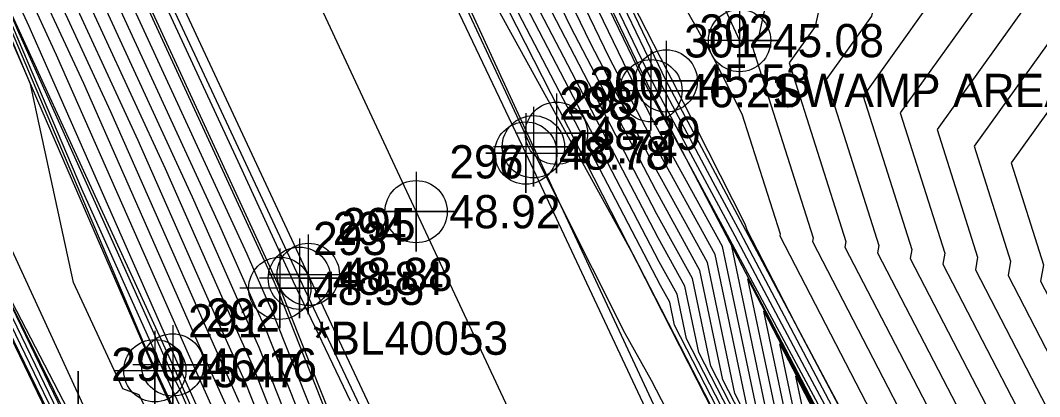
# Model space of a CAD drawing. Extents: x 2090860 to 2091277, y 159470 to 160080.
# Drawn here: x 2090993 to 2091069.7, y 159834.6 to 159862.9 of the extents above; entities that cross this region are included whole.
import ezdxf

# ---------------------------------------------------------------- set-up
doc = ezdxf.new("R2010")
doc.units = 0
for name, color, linetype in [('DTM Contours Major', 7, 'Continuous'), ('DTM Contours Minor', 7, 'Continuous'), ('Exist DTM Breakline', 7, 'Continuous'), ('Exist DTM Breakline Cogo Comment', 7, 'Continuous'), ('Exist DTM Breakline Cogo Elevation', 7, 'Continuous'), ('Exist DTM Breakline Cogo Number', 7, 'Continuous'), ('Exist DTM Breakline Cogo Point CELL', 7, 'Continuous'), ('Exist DTM Breakline Underwater', 7, 'Continuous'), ('Exist DTM Crownline', 7, 'Continuous'), ('Exist DTM Crownline Cogo Elevation', 7, 'Continuous'), ('Exist DTM Crownline Cogo Number', 7, 'Continuous'), ('Exist DTM Crownline Cogo Point CELL', 7, 'Continuous'), ('Exist Hydro Swamp or Marsh', 7, 'Continuous'), ('Exist Hydro Swamp or Marsh Cogo Number', 7, 'Continuous'), ('Exist Roads EOP', 7, 'Continuous'), ('Exist Roads EOP Cogo Elevation', 7, 'Continuous'), ('Exist Roads EOP Cogo Number', 7, 'Continuous'), ('Exist Roads EOP Cogo Point CELL', 7, 'Continuous'), ('Exist Roads EOT', 7, 'Continuous'), ('Exist Roads EOT Cogo Elevation', 7, 'Continuous'), ('Exist Roads EOT Cogo Number', 7, 'Continuous'), ('Exist Roads EOT Cogo Point CELL', 7, 'Continuous')]:
    doc.layers.add(name, color=color, linetype=linetype)

msp = doc.modelspace()

# ---------------------------------------------------------------- linework, layer by layer
at = {"layer": 'DTM Contours Major'}
for points in [[(2091039.965, 159928.181), (2091029.722, 159901.932), (2091029.836, 159894.927), (2091030.644, 159893.334), (2091041.091, 159874.328), (2091046.743, 159874.324), (2091051.278, 159874.322), (2091048.513, 159861.61), (2091048.021, 159860.923), (2091052.613, 159846.512), (2091052.563, 159846.236), (2091064.701, 159822.801), (2091063.816, 159819.49), (2091056.743, 159812.832), (2091055.874, 159811.447), (2091055.801, 159811.406), (2091054.881, 159810.97), (2091050.569, 159808.882), (2091033.907, 159797.012), (2091031.476, 159794.619), (2091026.533, 159778.36)], [(2091091.582, 159898.637), (2091075.464, 159895.754), (2091071.361, 159891.649), (2091065.515, 159864.769), (2091059.162, 159855.905), (2091062.527, 159845.344), (2091062.382, 159844.528), (2091071.24, 159827.424), (2091068.468, 159817.052), (2091062.553, 159811.484), (2091060.259, 159801.479), (2091046.876, 159791.945), (2091037.586, 159782.801), (2091031.987, 159764.384), (2091026.688, 159760.214), (2091021.294, 159752.688), (2091014.874, 159747.469), (2091001.671, 159730.125), (2090998.416, 159727.263), (2090990.823, 159719.668), (2090976.25, 159706.989)], [(2091056.078, 159816.651), (2091046.739, 159834.797), (2091044.672, 159844.658), (2091040.694, 159851.881), (2091035.836, 159861.213), (2091027.499, 159878.464)], [(2090991.853, 159864.196), (2090992.701, 159862.198), (2091004.114, 159836.848), (2091004.895, 159835.174), (2091007.518, 159829.269), (2091018.331, 159804.925), (2091019.741, 159801.878), (2091021.206, 159801.236), (2091025.093, 159800.189), (2091028.857, 159799.035), (2091029.349, 159799.339), (2091029.689, 159799.398), (2091044.087, 159806.371), (2091055.495, 159811.774), (2091056.395, 159812.282), (2091061.025, 159819.665), (2091060.533, 159819.671), (2091060.876, 159820.18), (2091051.784, 159837.119), (2091046.749, 159846.634), (2091042.53, 159854.466), (2091040.766, 159857.8), (2091031.335, 159877.368)], [(2091016.707, 159800.202), (2091008.385, 159811.907), (2091004.989, 159818.475), (2091002.257, 159829.041), (2091000.514, 159832.567), (2090997.856, 159833.556), (2090989.841, 159850.886), (2090987.897, 159859.839), (2090982.037, 159867.754), (2090974.898, 159876.535), (2090983.754, 159858.196), (2090986.806, 159851.928), (2090996.121, 159832.681), (2090997.829, 159829.173), (2090999.89, 159824.931), (2091004.415, 159815.535), (2091007.296, 159809.554), (2091015.202, 159792.842), (2091016.707, 159800.202)], [(2090998.152, 159868.688), (2091007.947, 159847.443), (2091010.62, 159841.379), (2091011.396, 159839.656), (2091019.854, 159818.29)], [(2090994.954, 159866.398), (2090999.747, 159856.003), (2091007.255, 159838.974), (2091009.433, 159834.136)], [(2091055.311, 159815.182), (2091043.096, 159838.914), (2091042.395, 159842.26), (2091041.045, 159844.711), (2091030.068, 159865.795)], [(2091047.708, 159843.434), (2091059.851, 159820.055), (2091059.262, 159819.226), (2091056.846, 159818.12), (2091050.382, 159830.679), (2091047.708, 159843.434)]]:
    msp.add_lwpolyline(points, dxfattribs=at)
at = {"layer": 'DTM Contours Minor'}
for points in [[(2090953.056, 159921.956), (2090965.045, 159895.337), (2090965.357, 159894.662), (2090965.917, 159893.402), (2090966.117, 159891.569), (2090966.399, 159891.209), (2090966.744, 159891.353), (2090970.598, 159883.648), (2090979.253, 159865.886), (2090979.998, 159864.343), (2090992.069, 159839.553), (2090993.271, 159837.069), (2090997.157, 159829.086), (2091001.847, 159819.434), (2091003.887, 159815.198), (2091014.815, 159792.51), (2091016.869, 159788.257), (2091017.431, 159786.838), (2091024.63, 159765.903)], [(2091018.49, 159801.202), (2091016.342, 159804.224), (2091005.914, 159824.395), (2091004.745, 159828.914), (2091001.892, 159834.689), (2091000.663, 159835.146), (2090996.957, 159843.159), (2090993.719, 159858.066), (2090991.183, 159864.043), (2090990.784, 159864.918), (2090986.104, 159875.843), (2090983.691, 159880.804), (2090975.225, 159897.621), (2090972.537, 159899.282), (2090971.355, 159899.978), (2090971.029, 159900.712), (2090971.838, 159903.298), (2090965.559, 159913.825)], [(2090957.425, 159912.812), (2090965.766, 159894.719), (2090966.215, 159893.707), (2090967.091, 159891.809), (2090969.426, 159886.946), (2090975.022, 159875.464), (2090981.876, 159861.269), (2090989.438, 159845.741), (2090994.696, 159834.875), (2090997.493, 159829.13), (2091000.868, 159822.182), (2091004.151, 159815.366), (2091012.999, 159796.996), (2091016.233, 159790.161), (2091018.49, 159801.202)], [(2091026.968, 159913.295), (2091027.29, 159893.598), (2091029.561, 159889.119), (2091036.393, 159876.69), (2091042.848, 159864.079), (2091045.034, 159860.22), (2091047.258, 159855.832), (2091050.134, 159846.804), (2091050.109, 159846.662), (2091063.066, 159821.645), (2091062.653, 159820.099), (2091059.35, 159816.99), (2091056.004, 159811.656), (2091055.725, 159811.498), (2091052.183, 159809.82), (2091035.577, 159801.778), (2091030.665, 159798.279), (2091029.949, 159797.574), (2091028.492, 159792.781), (2091019.078, 159782.234), (2091024.701, 159765.882)], [(2091085.63, 159904.476), (2091061.277, 159900.12), (2091060.882, 159899.725), (2091052.763, 159862.4), (2091050.806, 159859.669), (2091055.091, 159846.22), (2091055.018, 159845.809), (2091066.336, 159823.957), (2091064.979, 159818.88), (2091057.025, 159811.393), (2091056.616, 159809.613), (2091037.15, 159795.745), (2091033.004, 159791.665), (2091025.134, 159765.782), (2091024.911, 159765.606), (2091017.656, 159755.482), (2091016.238, 159754.329), (2090999.201, 159731.949), (2090995.001, 159728.257), (2090991.695, 159724.95), (2090972.197, 159707.986)], [(2091087.614, 159902.53), (2091066.006, 159898.665), (2091064.375, 159897.033), (2091057.014, 159863.189), (2091053.591, 159858.414), (2091057.57, 159845.928), (2091057.473, 159845.382), (2091067.971, 159825.113), (2091066.142, 159818.271), (2091058.867, 159811.424), (2091057.831, 159806.902), (2091040.392, 159794.478), (2091034.531, 159788.71), (2091027.419, 159765.316), (2091025.503, 159763.809), (2091018.868, 159754.551), (2091015.783, 159752.042), (2091000.024, 159731.341), (2090996.139, 159727.925), (2090991.404, 159723.189), (2090973.548, 159707.654)], [(2091089.598, 159900.583), (2091070.735, 159897.209), (2091067.868, 159894.341), (2091061.264, 159863.979), (2091056.377, 159857.16), (2091060.048, 159845.636), (2091059.927, 159844.955), (2091069.606, 159826.269), (2091067.305, 159817.661), (2091060.71, 159811.454), (2091059.045, 159804.19), (2091043.634, 159793.212), (2091036.059, 159785.755), (2091029.703, 159764.85), (2091026.095, 159762.012), (2091020.081, 159753.62), (2091015.328, 159749.755), (2091000.847, 159730.733), (2090997.277, 159727.594), (2090991.114, 159721.429), (2090974.899, 159707.322)], [(2091093.566, 159896.69), (2091080.192, 159894.298), (2091074.854, 159888.957), (2091069.765, 159865.558), (2091061.947, 159854.65), (2091065.005, 159845.052), (2091064.837, 159844.101), (2091072.875, 159828.58), (2091069.631, 159816.443), (2091064.396, 159811.515), (2091061.473, 159798.767), (2091050.118, 159790.678), (2091039.113, 159779.846), (2091034.271, 159763.918), (2091027.28, 159758.417), (2091022.507, 159751.757), (2091014.419, 159745.182), (2091002.494, 159729.516), (2090999.554, 159726.932), (2090990.532, 159717.907), (2090977.601, 159706.657)], [(2091095.549, 159894.744), (2091084.921, 159892.843), (2091078.348, 159886.266), (2091074.015, 159866.348), (2091064.733, 159853.396), (2091067.484, 159844.76), (2091067.291, 159843.674), (2091074.51, 159829.736), (2091070.794, 159815.833), (2091066.238, 159811.545), (2091062.688, 159796.056), (2091053.36, 159789.411), (2091040.641, 159776.892), (2091036.555, 159763.452), (2091027.872, 159756.62), (2091023.719, 159750.826), (2091013.964, 159742.895), (2091003.317, 159728.908), (2091000.692, 159726.601), (2090990.241, 159716.147), (2090978.952, 159706.325)], [(2091097.533, 159892.797), (2091089.65, 159891.387), (2091081.841, 159883.574), (2091078.266, 159867.137), (2091067.518, 159852.141), (2091069.963, 159844.468), (2091069.746, 159843.247), (2091076.145, 159830.892), (2091071.957, 159815.224), (2091068.081, 159811.575), (2091063.902, 159793.344), (2091056.602, 159788.144), (2091042.168, 159773.937), (2091038.839, 159762.987), (2091028.464, 159754.823), (2091024.932, 159749.895), (2091013.509, 159740.608), (2091004.14, 159728.3), (2091001.83, 159726.269), (2090989.951, 159714.386), (2090980.303, 159705.993)], [(2090992.556, 159864.681), (2090993.597, 159862.423), (2091004.731, 159837.17), (2091007.961, 159829.995), (2091008.468, 159828.714), (2091020.08, 159802.837), (2091021.254, 159801.443), (2091021.996, 159801.118), (2091023.46, 159800.723), (2091028.681, 159799.123), (2091029.364, 159799.544), (2091029.836, 159799.626), (2091041.388, 159805.221), (2091055.419, 159811.866), (2091056.526, 159812.491), (2091060.739, 159819.209), (2091060.015, 159819.218), (2091060.519, 159819.967), (2091047.146, 159844.881), (2091046.348, 159846.389), (2091043.245, 159852.15), (2091040.431, 159857.259), (2091040.162, 159857.776), (2091027.446, 159884.088)], [(2091048.56, 159832.738), (2091045.81, 159845.857), (2091040.519, 159855.466), (2091038.72, 159858.921), (2091027.464, 159882.213)], [(2091052.347, 159812.818), (2091040.46, 159835.77), (2091038.477, 159839.311), (2091033.536, 159849.139), (2091031.44, 159853.253), (2091029.679, 159857.091), (2091018.757, 159880.423)], [(2091047.65, 159833.767), (2091045.241, 159845.257), (2091040.607, 159853.673), (2091037.278, 159860.067), (2091027.481, 159880.338)], [(2091055.886, 159816.284), (2091045.828, 159835.826), (2091044.102, 159844.058), (2091040.782, 159850.088), (2091034.394, 159862.358), (2091027.517, 159876.589)], [(2091061.059, 159821.595), (2091051.606, 159839.459), (2091047.654, 159847.089), (2091047.655, 159847.096), (2091047.517, 159847.529), (2091041.945, 159858.526), (2091041.704, 159858.952), (2091034.703, 159872.628)], [(2091000.895, 159870.46), (2091009.465, 159851.941), (2091013.483, 159843.225), (2091017.769, 159834.238)], [(2090999.751, 159869.832), (2091012.046, 159843.163), (2091012.303, 159842.582), (2091012.377, 159842.416), (2091023.107, 159815.311)], [(2090998.952, 159869.26), (2091009.997, 159845.303), (2091011.461, 159841.98), (2091011.886, 159841.036), (2091021.481, 159816.8)], [(2090996.553, 159867.543), (2091003.847, 159851.723), (2091008.937, 159840.176), (2091010.414, 159836.896), (2091016.601, 159821.268)], [(2090997.353, 159868.115), (2091005.897, 159849.583), (2091009.779, 159840.778), (2091010.905, 159838.276), (2091018.227, 159819.779)], [(2090991.629, 159864.145), (2090997.549, 159850.196), (2091003.629, 159836.691), (2091005.654, 159832.353), (2091007.113, 159829.069), (2091013.126, 159815.531), (2091019.504, 159801.754), (2091020.416, 159801.354), (2091026.726, 159799.654), (2091029.032, 159798.948), (2091029.334, 159799.133), (2091029.542, 159799.17), (2091046.785, 159807.521), (2091055.572, 159811.682), (2091056.265, 159812.074), (2091061.312, 159820.121), (2091061.051, 159820.124), (2091061.233, 159820.393), (2091056.421, 159829.357), (2091047.15, 159846.879), (2091045.095, 159850.693), (2091041.19, 159858.075), (2091036.787, 159867.212)], [(2090995.754, 159866.971), (2091001.797, 159853.863), (2091008.096, 159839.575), (2091009.924, 159835.516), (2091014.974, 159822.757)], [(2091055.119, 159814.815), (2091042.185, 159839.944), (2091041.825, 159841.661), (2091041.133, 159842.918), (2091028.626, 159866.941)], [(2090993.355, 159865.254), (2090995.647, 159860.283), (2091005.572, 159837.771), (2091008.452, 159831.375)], [(2090994.155, 159865.826), (2090997.697, 159858.143), (2091006.414, 159838.372), (2091008.943, 159832.756)], [(2091054.927, 159814.447), (2091041.274, 159840.973), (2091041.256, 159841.061), (2091041.221, 159841.126), (2091039.076, 159845.244), (2091028.516, 159864.43)], [(2091055.503, 159815.549), (2091044.007, 159837.885), (2091042.964, 159842.86), (2091040.958, 159846.503), (2091031.51, 159864.649)], [(2090991.406, 159864.094), (2091002.397, 159838.193), (2091003.144, 159836.535), (2091006.413, 159829.532)], [(2091055.694, 159815.916), (2091044.917, 159836.856), (2091043.533, 159843.459), (2091040.87, 159848.296), (2091032.952, 159863.504)], [(2090989.86, 159846.37), (2090997.915, 159830.901), (2090999.137, 159830.446), (2090999.768, 159829.169), (2091001.594, 159822.11), (2090998.911, 159827.68), (2090998.164, 159829.216), (2090997.546, 159830.487), (2090989.86, 159846.37)], [(2091046.5, 159845.882), (2091059.993, 159819.903), (2091059.339, 159818.981), (2091056.654, 159817.753), (2091049.471, 159831.708), (2091046.5, 159845.882)], [(2091048.916, 159840.986), (2091059.709, 159820.207), (2091059.185, 159819.47), (2091057.038, 159818.487), (2091051.292, 159829.649), (2091048.916, 159840.986)], [(2091050.124, 159838.538), (2091059.566, 159820.359), (2091059.108, 159819.714), (2091057.229, 159818.854), (2091052.203, 159828.62), (2091050.124, 159838.538)], [(2091051.332, 159836.09), (2091059.424, 159820.511), (2091059.031, 159819.958), (2091057.421, 159819.222), (2091053.114, 159827.59), (2091051.332, 159836.09)]]:
    msp.add_lwpolyline(points, dxfattribs=at)
at = {"layer": 'Exist DTM Breakline'}
for p, q in [((2090966.689, 159891.716), (2090997.039, 159829.071)), ((2090998.355, 159829.241), (2090967.299, 159891.857)), ((2091012.481, 159842.709), (2091028.915, 159801.572))]:
    msp.add_line(p, q, dxfattribs=at)
for points in [[(2091060.143, 159819.743), (2091040.416, 159857.574), (2091023.862, 159892.084), (2091004.981, 159933.927), (2090988.922, 159970.746), (2090947.972, 160061.797)], [(2091061.634, 159820.633), (2091041.562, 159858.316), (2091025.181, 159892.498), (2091005.429, 159934.281), (2090989.687, 159971.201), (2090948.616, 160062.008)], [(2091054.851, 159814.302), (2091016.781, 159888.977), (2090997.773, 159930.425), (2090980.346, 159966.514), (2090937.845, 160056.578)], [(2091012.481, 159842.709), (2090995.611, 159879.293), (2090976.725, 159918.896), (2090959.8, 159955.653), (2090940.36, 159997.15), (2090917.627, 160046.575)], [(2091019.111, 159801.55), (2091003.076, 159836.513), (2090986.016, 159875.809), (2090966.872, 159914.505), (2090949.073, 159951.294), (2090930.109, 159992.15), (2090906.432, 160041.549)], [(2091019.809, 159801.913), (2091004.418, 159836.946), (2090986.475, 159875.987), (2090967.517, 159915.028), (2090950.041, 159951.449), (2090930.695, 159992.433), (2090908.049, 160042.233)]]:
    msp.add_lwpolyline(points, dxfattribs=at)
at = {"layer": 'Exist DTM Breakline Cogo Point CELL'}
for points in [[(2091047.085, 159864.345), (2091047.085, 159858.345), (2091047.085, 159861.345), (2091050.085, 159861.345), (2091044.085, 159861.345)], [(2091041.562, 159861.316), (2091041.562, 159855.316), (2091041.562, 159858.316), (2091044.562, 159858.316), (2091038.562, 159858.316)], [(2091040.416, 159860.574), (2091040.416, 159854.574), (2091040.416, 159857.574), (2091043.416, 159857.574), (2091037.416, 159857.574)], [(2091033.298, 159857.372), (2091033.298, 159851.372), (2091033.298, 159854.372), (2091036.298, 159854.372), (2091030.298, 159854.372)], [(2091012.481, 159845.709), (2091012.481, 159839.709), (2091012.481, 159842.709), (2091015.481, 159842.709), (2091009.481, 159842.709)], [(2091004.418, 159839.946), (2091004.418, 159833.946), (2091004.418, 159836.946), (2091007.418, 159836.946), (2091001.418, 159836.946)], [(2091003.076, 159839.513), (2091003.076, 159833.513), (2091003.076, 159836.513), (2091006.076, 159836.513), (2091000.076, 159836.513)]]:
    msp.add_lwpolyline(points, dxfattribs=at)
for centre in [(2091047.085, 159861.345), (2091041.562, 159858.316), (2091040.416, 159857.574), (2091033.298, 159854.372), (2091012.481, 159842.709), (2091004.418, 159836.946), (2091003.076, 159836.513)]:
    msp.add_circle(centre, 2.344, dxfattribs=at)
at = {"layer": 'Exist DTM Breakline Underwater'}
msp.add_lwpolyline([(2091025.272, 159920.294), (2091031.242, 159895.66), (2091047.085, 159861.345)], dxfattribs=at)
at = {"layer": 'Exist DTM Crownline'}
msp.add_lwpolyline([(2091041.896, 159807.58), (2091022.738, 159848.476), (2091006.16, 159884.052), (2090987.202, 159924.29), (2090970.349, 159960.929), (2090951.234, 160001.943), (2090928.333, 160051.748)], dxfattribs=at)
at = {"layer": 'Exist DTM Crownline Cogo Point CELL'}
msp.add_lwpolyline([(2091022.738, 159851.476), (2091022.738, 159845.476), (2091022.738, 159848.476), (2091025.738, 159848.476), (2091019.738, 159848.476)], dxfattribs=at)
msp.add_circle((2091022.738, 159848.476), 2.344, dxfattribs=at)
at = {"layer": 'Exist Hydro Swamp or Marsh'}
msp.add_lwpolyline([(2090994.07, 159830.564), (2090997.296, 159830.564), (2090997.296, 159836.481), (2090997.296, 159830.564), (2091000.521, 159830.564)], dxfattribs=at)
at = {"layer": 'Exist Roads EOP'}
for points in [[(2091050.887, 159811.953), (2091031.567, 159853.358), (2091015.44, 159888.433), (2090996.018, 159929.558), (2090979.118, 159965.859), (2090960.144, 160006.791), (2090936.877, 160056.11)], [(2091032.873, 159803.467), (2091013.956, 159843.468), (2090996.901, 159879.939), (2090978.321, 159919.673), (2090961.239, 159956.493), (2090941.84, 159997.888), (2090918.792, 160047.284)]]:
    msp.add_lwpolyline(points, dxfattribs=at)
at = {"layer": 'Exist Roads EOP Cogo Point CELL'}
for points in [[(2091031.567, 159856.358), (2091031.567, 159850.358), (2091031.567, 159853.358), (2091034.567, 159853.358), (2091028.567, 159853.358)], [(2091013.956, 159846.468), (2091013.956, 159840.468), (2091013.956, 159843.468), (2091016.956, 159843.468), (2091010.956, 159843.468)]]:
    msp.add_lwpolyline(points, dxfattribs=at)
for centre in [(2091031.567, 159853.358), (2091013.956, 159843.468)]:
    msp.add_circle(centre, 2.344, dxfattribs=at)
at = {"layer": 'Exist Roads EOT'}
for points in [[(2091050.358, 159811.619), (2091030.997, 159852.885), (2091014.318, 159887.944), (2090995.228, 159929.102), (2090978.274, 159965.509), (2090959.414, 160006.451), (2090936.296, 160055.791)], [(2091033.429, 159803.706), (2091014.624, 159843.758), (2090997.608, 159880.208), (2090978.895, 159919.952), (2090961.789, 159956.632), (2090942.516, 159998.302), (2090919.608, 160047.643)]]:
    msp.add_lwpolyline(points, dxfattribs=at)
at = {"layer": 'Exist Roads EOT Cogo Point CELL'}
for points in [[(2091030.997, 159855.885), (2091030.997, 159849.885), (2091030.997, 159852.885), (2091027.997, 159852.885), (2091033.997, 159852.885)], [(2091022.738, 159851.476), (2091022.738, 159845.476), (2091022.738, 159848.476), (2091019.738, 159848.476), (2091025.738, 159848.476)], [(2091014.624, 159846.758), (2091014.624, 159840.758), (2091014.624, 159843.758), (2091011.624, 159843.758), (2091017.624, 159843.758)]]:
    msp.add_lwpolyline(points, dxfattribs=at)
for centre in [(2091030.997, 159852.885), (2091022.738, 159848.476), (2091014.624, 159843.758)]:
    msp.add_circle(centre, 2.344, dxfattribs=at)

# ---------------------------------------------------------------- texts
at = {"layer": 'Exist DTM Breakline Cogo Comment'}
for s, p in [('SWAMP AREA', (2091049.585, 159856.345)), ('*BL40053', (2091014.981, 159837.709))]:
    msp.add_text(s, height=2.5, dxfattribs=at).set_placement(p)
at = {"layer": 'Exist DTM Breakline Cogo Elevation'}
for s, p in [('45.08', (2091049.585, 159860.095)), ('45.53', (2091044.062, 159857.066)), ('46.21', (2091042.916, 159856.324)), ('48.39', (2091035.798, 159853.122)), ('48.55', (2091014.981, 159841.459)), ('45.47', (2091005.576, 159835.263)), ('46.16', (2091006.918, 159835.696))]:
    msp.add_text(s, height=2.5, dxfattribs=at).set_placement(p)
at = {"layer": 'Exist DTM Breakline Cogo Number'}
for s, p in [('302', (2091044.062, 159860.816)), ('301', (2091042.916, 159860.074)), ('300', (2091035.798, 159856.872)), ('293', (2091014.981, 159845.209)), ('291', (2091005.576, 159839.013)), ('292', (2091006.918, 159839.446))]:
    msp.add_text(s, height=2.5, dxfattribs=at).set_placement(p)
at = {"layer": 'Exist DTM Crownline Cogo Elevation'}
msp.add_text('48.92', height=2.5, dxfattribs=at).set_placement((2091025.238, 159847.226))
at = {"layer": 'Exist DTM Crownline Cogo Number'}
msp.add_text('297', height=2.5, dxfattribs=at).set_placement((2091025.238, 159850.976))
at = {"layer": 'Exist Hydro Swamp or Marsh Cogo Number'}
msp.add_text('290', height=2.5, dxfattribs=at).set_placement((2090999.795, 159835.738))
at = {"layer": 'Exist Roads EOP Cogo Elevation'}
for s, p in [('48.74', (2091034.067, 159852.108)), ('48.84', (2091016.456, 159842.218))]:
    msp.add_text(s, height=2.5, dxfattribs=at).set_placement(p)
at = {"layer": 'Exist Roads EOP Cogo Number'}
for s, p in [('299', (2091034.067, 159855.858)), ('294', (2091016.456, 159845.968))]:
    msp.add_text(s, height=2.5, dxfattribs=at).set_placement(p)
at = {"layer": 'Exist Roads EOT Cogo Elevation'}
for s, p in [('48.78', (2091033.497, 159851.635)), ('48.92', (2091025.238, 159847.226)), ('48.88', (2091017.124, 159842.508))]:
    msp.add_text(s, height=2.5, dxfattribs=at).set_placement(p)
at = {"layer": 'Exist Roads EOT Cogo Number'}
for s, p in [('298', (2091033.497, 159855.385)), ('296', (2091025.238, 159850.976)), ('295', (2091017.124, 159846.258))]:
    msp.add_text(s, height=2.5, dxfattribs=at).set_placement(p)

doc.saveas('drawing.dxf')
